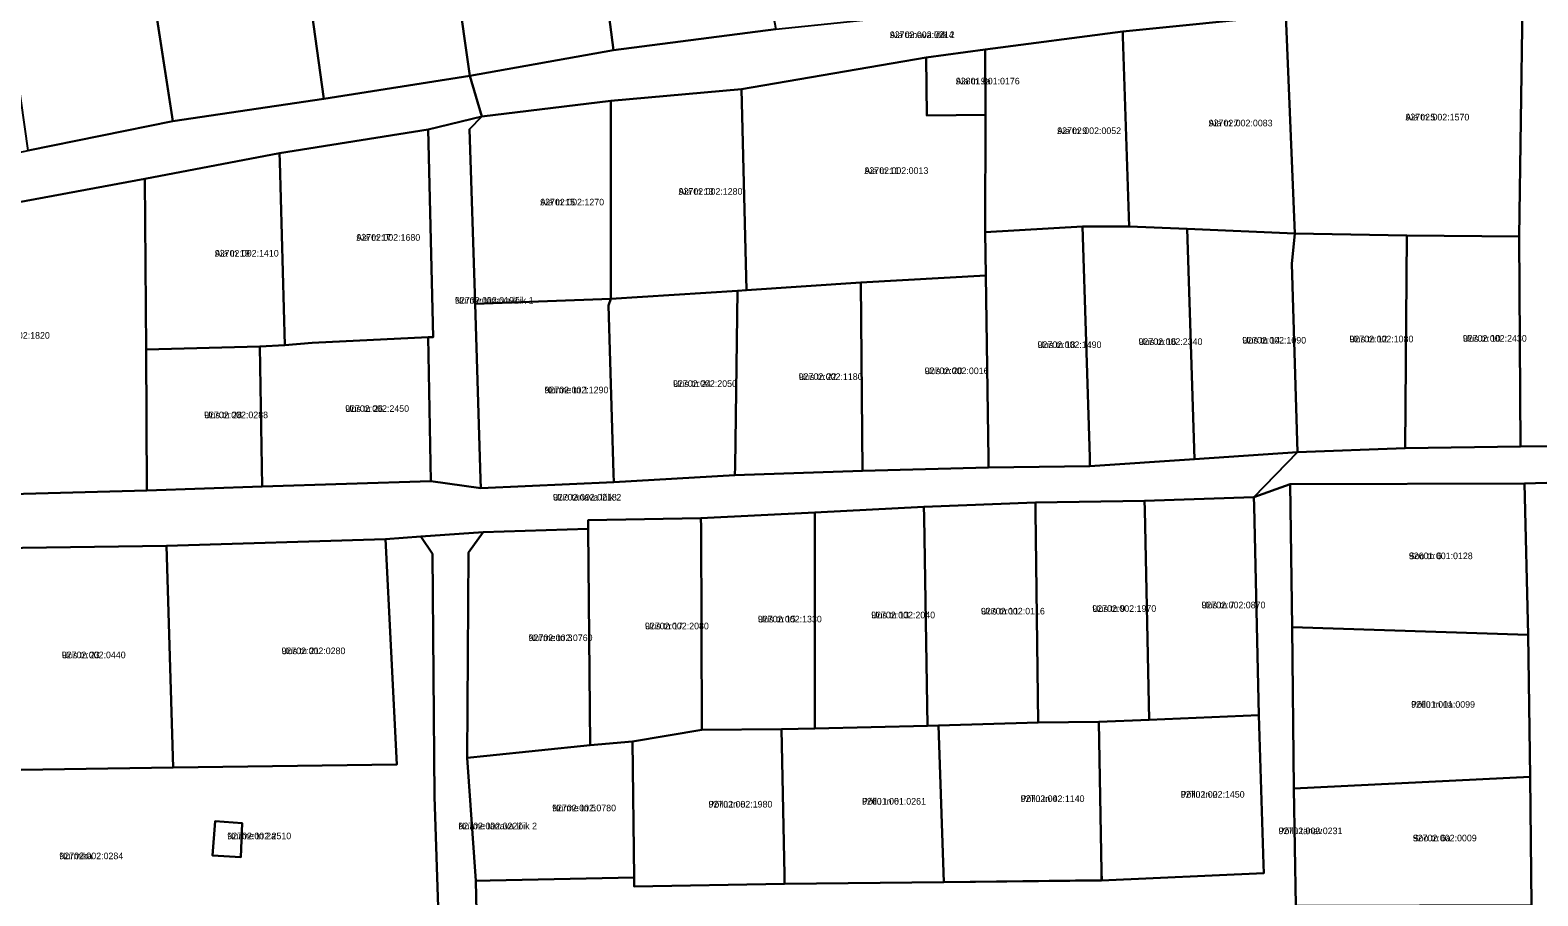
# Model space of a CAD drawing. Extents: x 615668 to 650289, y 6528908 to 6565939.
# Drawn here: x 628269.6 to 628611.8, y 6556139.7 to 6556336.2 of the extents above; entities that cross this region are included whole.
import ezdxf

# ---------------------------------------------------------------- set-up
doc = ezdxf.new("R2010")
doc.units = 0
for name, color, linetype in [('L_AADRESS', 7, 'Continuous'), ('PIIR', 7, 'Continuous'), ('TUNNUS', 7, 'Continuous')]:
    doc.layers.add(name, color=color, linetype=linetype)

msp = doc.modelspace()

# ---------------------------------------------------------------- linework, layer by layer
at = {"layer": 'PIIR'}
for points in [[(628402.02, 6556331.66), (628394.45, 6556390.11), (628427.95, 6556393.66), (628438.91, 6556336.43)], [(628369.45, 6556325.85), (628360.78, 6556386.55), (628377.58, 6556388.32), (628394.45, 6556390.11), (628402.02, 6556331.66)], [(628369.45, 6556325.85), (628336.3, 6556320.66), (628329.69, 6556368.05), (628327.48, 6556383.9), (628352.69, 6556385.91), (628360.78, 6556386.55)], [(628336.3, 6556320.66), (628302, 6556315.55), (628294.76, 6556362.62), (628294.62, 6556363.75), (628329.69, 6556368.05)], [(628262.17, 6556360.83), (628286.06, 6556362.6), (628294.62, 6556363.75), (628302, 6556315.55), (628269.18, 6556308.92), (628263.49, 6556349.22)], [(628369.45, 6556325.85), (628402.02, 6556331.66), (628438.91, 6556336.43), (628454.99, 6556338.1), (628499.26, 6556342.73), (628518.54, 6556345.4), (628521.42, 6556345.66), (628550.07, 6556348.55), (628583.13, 6556351.45), (628588.61, 6556351.54), (628613.32, 6556352.2), (628617.38, 6556341.82), (628608.35, 6556342.06), (628554.61, 6556339.61), (628517.62, 6556335.92), (628486.41, 6556331.82), (628472.97, 6556329.99), (628431.06, 6556322.79), (628401.41, 6556320.14), (628372.17, 6556316.63)], [(628517.62, 6556335.92), (628554.61, 6556339.61), (628556.65, 6556290.09), (628532.21, 6556291.1), (628519.1, 6556291.63), (628517.65, 6556334.77)], [(628556.65, 6556290.09), (628554.61, 6556339.61), (628608.35, 6556342.06), (628607.63, 6556289.38), (628582.13, 6556289.58)], [(628617.38, 6556341.82), (628619.17, 6556299.87), (628618.82, 6556245.13), (628621.11, 6556241.84), (628607.91, 6556241.68), (628607.63, 6556289.38), (628608.35, 6556342.06)], [(628486.41, 6556331.82), (628517.62, 6556335.92), (628517.65, 6556334.77), (628519.1, 6556291.63), (628508.5, 6556291.64), (628486.4, 6556290.34), (628486.5, 6556316.96)], [(628432.2, 6556277.17), (628431.06, 6556322.79), (628472.97, 6556329.99), (628473.19, 6556316.83), (628486.5, 6556316.96), (628486.4, 6556290.34), (628486.55, 6556280.55), (628458.15, 6556278.92)], [(628472.97, 6556329.99), (628486.41, 6556331.82), (628486.5, 6556316.96), (628473.19, 6556316.83)], [(628116.78, 6556276.3), (628127.45, 6556279.02), (628161.18, 6556285.75), (628193.23, 6556292.27), (628215.47, 6556296.93), (628241.75, 6556303.04), (628269.18, 6556308.92), (628302, 6556315.55), (628336.3, 6556320.66), (628369.45, 6556325.85), (628372.17, 6556316.63), (628359.94, 6556313.66), (628326.25, 6556308.32), (628295.63, 6556302.48), (628222.97, 6556288.97), (628167.18, 6556276.26), (628166.92, 6556277.13), (628127.61, 6556268.99), (628117.78, 6556267.72)], [(628401.41, 6556320.14), (628431.06, 6556322.79), (628432.2, 6556277.17), (628430.2, 6556277.01), (628401.4, 6556275.22)], [(628369.38, 6556313.76), (628372.17, 6556316.63), (628401.41, 6556320.14), (628401.4, 6556275.22), (628370.64, 6556274.1)], [(628359.94, 6556313.66), (628372.17, 6556316.63), (628369.38, 6556313.76), (628370.64, 6556274.1), (628371.84, 6556234.29), (628371.9, 6556232.29), (628360.57, 6556233.84), (628359.94, 6556266.5), (628361.06, 6556266.55)], [(628359.94, 6556313.66), (628361.06, 6556266.55), (628359.94, 6556266.5), (628333.64, 6556265.27), (628327.43, 6556264.7), (628326.31, 6556306.34), (628326.25, 6556308.32)], [(628295.63, 6556302.48), (628326.25, 6556308.32), (628326.31, 6556306.34), (628327.43, 6556264.7), (628321.74, 6556264.39), (628295.97, 6556263.72)], [(628223.57, 6556229.86), (628222.98, 6556288.5), (628222.97, 6556288.97), (628295.63, 6556302.48), (628295.97, 6556263.72), (628296.13, 6556231.76), (628251.22, 6556230.55)], [(628508.5, 6556291.64), (628510.13, 6556239.26), (628510.19, 6556237.26), (628487.18, 6556236.92), (628487.15, 6556238.92), (628486.55, 6556280.55), (628486.4, 6556290.34)], [(628510.13, 6556239.26), (628508.5, 6556291.64), (628519.1, 6556291.63), (628532.21, 6556291.1), (628533.92, 6556238.84), (628510.19, 6556237.26)], [(628532.21, 6556291.1), (628556.65, 6556290.09), (628556.04, 6556283.17), (628557.28, 6556240.42), (628533.92, 6556238.84)], [(628556.04, 6556283.17), (628556.65, 6556290.09), (628582.13, 6556289.58), (628581.74, 6556241.37), (628557.28, 6556240.42)], [(628582.13, 6556289.58), (628607.63, 6556289.38), (628607.91, 6556241.68), (628581.74, 6556241.37)], [(628429.63, 6556237.19), (628430.2, 6556277.01), (628432.2, 6556277.17), (628458.15, 6556278.92), (628458.53, 6556236.16), (628429.6, 6556235.19)], [(628458.53, 6556236.16), (628458.15, 6556278.92), (628486.55, 6556280.55), (628487.15, 6556238.92), (628487.18, 6556236.92)], [(628371.84, 6556234.29), (628370.64, 6556274.1), (628401.4, 6556275.22), (628400.91, 6556273.69), (628402.03, 6556235.6), (628402.09, 6556233.6), (628371.9, 6556232.29)], [(628402.03, 6556235.6), (628400.91, 6556273.69), (628401.4, 6556275.22), (628430.2, 6556277.01), (628429.63, 6556237.19), (628429.6, 6556235.19), (628402.09, 6556233.6)], [(628295.97, 6556263.72), (628321.74, 6556264.39), (628322.26, 6556232.63), (628296.13, 6556231.76)], [(628321.74, 6556264.39), (628327.43, 6556264.7), (628333.64, 6556265.27), (628359.94, 6556266.5), (628360.57, 6556233.84), (628322.26, 6556232.63)], [(628742.72, 6556235.1), (628740.01, 6556238.08), (628738.77, 6556234.25), (628736.92, 6556235.8), (628707.91, 6556235.32), (628678.17, 6556235.14), (628673.59, 6556234.1), (628616.36, 6556233.56), (628608.85, 6556233.28), (628555.62, 6556233.14), (628547.38, 6556230.2), (628557.28, 6556240.42), (628581.74, 6556241.37), (628607.91, 6556241.68), (628621.11, 6556241.84), (628641.56, 6556242.21), (628663.69, 6556242.63), (628686.39, 6556242.91), (628739.87, 6556243.93), (628739.55, 6556242.37), (628743.81, 6556242.51)], [(628608.85, 6556233.28), (628609.65, 6556199), (628556.08, 6556200.7), (628555.62, 6556233.14)], [(628616.36, 6556233.56), (628616.56, 6556165.75), (628616.4, 6556137.36), (628616.36, 6556130.89), (628616.23, 6556108.71), (628610.81, 6556105.7), (628610.63, 6556120.99), (628610.43, 6556137.57), (628610.09, 6556166.71), (628609.65, 6556199), (628608.85, 6556233.28)], [(628251.22, 6556230.55), (628251.48, 6556218.47), (628252.68, 6556168.09), (628302.09, 6556168.82), (628352.81, 6556169.57), (628350.31, 6556220.66), (628358.28, 6556221.27), (628360.98, 6556217.37), (628361.36, 6556162.3), (628363.16, 6556109.78), (628368.29, 6556078.96), (628130.78, 6556065.52), (628125.16, 6556114.7), (628191.72, 6556114.13), (628189.74, 6556175.67), (628224.11, 6556176.37), (628223.57, 6556229.86)], [(628523.62, 6556179.64), (628522.61, 6556227.35), (628522.54, 6556229.35), (628547.38, 6556230.2), (628547.42, 6556228.15), (628548.48, 6556180.76)], [(628421.88, 6556225.42), (628447.73, 6556226.74), (628447.73, 6556224.74), (628447.73, 6556177.7), (628440.14, 6556177.53), (628422.06, 6556177.37), (628421.91, 6556223.43)], [(628447.73, 6556224.74), (628447.73, 6556226.74), (628472.47, 6556228.02), (628472.52, 6556225.68), (628473.32, 6556178.34), (628447.73, 6556177.7)], [(628497.83, 6556228.97), (628497.85, 6556226.97), (628498.41, 6556179.04), (628475.77, 6556178.4), (628473.32, 6556178.34), (628472.52, 6556225.68), (628472.47, 6556228.02)], [(628497.85, 6556226.97), (628497.83, 6556228.97), (628522.54, 6556229.35), (628522.61, 6556227.35), (628523.62, 6556179.64), (628512.19, 6556179.2), (628498.41, 6556179.04)], [(628373.29, 6556171.5), (628368.82, 6556171.04), (628369.15, 6556217.62), (628372.48, 6556222.28), (628396.28, 6556223.01), (628396.73, 6556173.95)], [(628396.73, 6556173.95), (628396.28, 6556223.01), (628396.28, 6556225.01), (628421.88, 6556225.42), (628421.91, 6556223.43), (628422.06, 6556177.37), (628406.33, 6556174.75)], [(628251.48, 6556218.47), (628300.53, 6556219.2), (628302.09, 6556168.82), (628252.68, 6556168.09)], [(628350.31, 6556220.66), (628352.81, 6556169.57), (628302.09, 6556168.82), (628300.53, 6556219.2)], [(628372.48, 6556222.28), (628369.15, 6556217.62), (628368.82, 6556171.04), (628370.81, 6556143.09), (628371, 6556132.6), (628370.96, 6556109.93), (628375.36, 6556079.42), (628368.29, 6556078.96), (628363.16, 6556109.78), (628361.36, 6556162.3), (628360.98, 6556217.37), (628358.28, 6556221.27)], [(628556.48, 6556164.12), (628556.08, 6556200.7), (628609.65, 6556199), (628610.09, 6556166.71)], [(628475.77, 6556178.4), (628477.01, 6556142.86), (628440.81, 6556142.47), (628440.84, 6556144.51), (628440.14, 6556177.53), (628447.73, 6556177.7), (628473.32, 6556178.34)], [(628475.77, 6556178.4), (628498.41, 6556179.04), (628512.19, 6556179.2), (628512.8, 6556145.27), (628512.84, 6556143.26), (628477.01, 6556142.86)], [(628512.8, 6556145.27), (628512.19, 6556179.2), (628523.62, 6556179.64), (628548.48, 6556180.76), (628549.56, 6556146.84), (628549.62, 6556144.84), (628512.78, 6556143.23)], [(628370.81, 6556143.09), (628368.82, 6556171.04), (628373.29, 6556171.5), (628396.73, 6556173.95), (628406.33, 6556174.75), (628406.7, 6556143.86), (628374.02, 6556143.23)], [(628406.73, 6556141.86), (628406.7, 6556143.86), (628406.33, 6556174.75), (628422.06, 6556177.37), (628440.14, 6556177.53), (628440.84, 6556144.51), (628440.81, 6556142.47)], [(628556.48, 6556164.12), (628610.09, 6556166.71), (628610.43, 6556137.57), (628559.51, 6556137.48), (628556.9, 6556137.47)], [(628317.72, 6556156.25), (628317.44, 6556148.48), (628311.02, 6556148.89), (628311.61, 6556156.65)], [(628311.61, 6556156.65), (628311.02, 6556148.89), (628317.44, 6556148.48), (628317.72, 6556156.25)]]:
    msp.add_lwpolyline(points, close=True, dxfattribs=at)
for points in [[(628251.22, 6556230.55), (628296.13, 6556231.76), (628322.26, 6556232.63), (628360.57, 6556233.84), (628371.9, 6556232.29), (628402.09, 6556233.6), (628429.6, 6556235.19), (628458.53, 6556236.16), (628487.18, 6556236.92), (628510.19, 6556237.26), (628533.92, 6556238.84), (628557.28, 6556240.42), (628547.38, 6556230.2), (628522.54, 6556229.35), (628497.83, 6556228.97), (628472.47, 6556228.02), (628447.73, 6556226.74), (628421.88, 6556225.42), (628396.28, 6556225.01), (628396.28, 6556223.01), (628372.48, 6556222.28), (628358.28, 6556221.27), (628350.31, 6556220.66), (628300.53, 6556219.2), (628251.48, 6556218.47)], [(628371, 6556132.6), (628370.81, 6556143.09), (628374.02, 6556143.23), (628406.7, 6556143.86), (628406.73, 6556141.86), (628440.81, 6556142.47), (628477.01, 6556142.86), (628512.78, 6556143.23), (628549.62, 6556144.84), (628549.56, 6556146.84), (628548.48, 6556180.76), (628547.42, 6556228.15), (628547.38, 6556230.2), (628555.62, 6556233.14), (628556.08, 6556200.7), (628556.48, 6556164.12), (628556.9, 6556137.47)]]:
    msp.add_lwpolyline(points, dxfattribs=at)

# ---------------------------------------------------------------- texts
at = {"layer": 'L_AADRESS'}
for s, p in [('Aia tänava lõik 2', (628464.75, 6556334.41)), ('Aia tn 9a', (628479.73, 6556323.9)), ('Aia tn 7', (628537.13, 6556314.38)), ('Aia tn 5', (628581.79, 6556315.72)), ('Aia tn 9', (628502.75, 6556312.63)), ('Aia tn 11', (628458.99, 6556303.58)), ('Aia tn 15', (628385.39, 6556296.43)), ('Aia tn 13', (628416.8, 6556298.85)), ('Aia tn 17', (628343.66, 6556288.41)), ('Aia tn 19', (628311.53, 6556284.82)), ('Nurme tänava lõik 1', (628366.05, 6556274.12)), ('Uus tn 10', (628594.82, 6556265.5)), ('Uus tn 18', (628498.29, 6556264.06)), ('Uus tn 16', (628521.21, 6556264.77)), ('Uus tn 14', (628544.75, 6556265.08)), ('Uus tn 12', (628569.09, 6556265.36)), ('Uus tn 24', (628415.55, 6556255.24)), ('Uus tn 22', (628444.07, 6556256.82)), ('Uus tn 20', (628472.66, 6556258.14)), ('Nurme tn 1', (628386.37, 6556253.8)), ('Uus tn 26', (628341.12, 6556249.57)), ('Uus tn 28', (628309.11, 6556248.13)), ('Uue tänava lõik 2', (628388.28, 6556229.45)), ('Soo tn 6', (628582.56, 6556216.14)), ('Uus tn 9', (628510.72, 6556204.18)), ('Uus tn 7', (628535.51, 6556204.98)), ('Uus tn 15', (628434.8, 6556201.78)), ('Uus tn 13', (628460.52, 6556202.71)), ('Uus tn 11', (628485.44, 6556203.59)), ('Nurme tn 3', (628382.77, 6556197.54)), ('Uus tn 17', (628409.17, 6556200.22)), ('Uus tn 23', (628276.79, 6556193.65)), ('Uus tn 21', (628326.67, 6556194.58)), ('Põllu tn 1a', (628583.08, 6556182.41)), ('Põllu tn 8', (628423.59, 6556159.77)), ('Põllu tn 6', (628458.45, 6556160.43)), ('Põllu tn 4', (628494.45, 6556161.03)), ('Põllu tn 2', (628530.79, 6556162)), ('Nurme tn 5', (628388.1, 6556158.92)), ('Nurme tn 2a', (628314.37, 6556152.57)), ('Nurme tänava lõik 2', (628366.82, 6556154.83)), ('Põllu tänav', (628552.99, 6556153.72)), ('Soo tn 6a', (628583.47, 6556152.09)), ('Nurmika', (628276.24, 6556148.04))]:
    msp.add_text(s, height=1.5, dxfattribs=at).set_placement(p)
at = {"layer": 'TUNNUS'}
for s, p in [('92702:002:0214', (628464.75, 6556334.41)), ('92801:001:0176', (628479.73, 6556323.9)), ('92702:002:0083', (628537.13, 6556314.38)), ('92702:002:1570', (628581.79, 6556315.72)), ('92702:002:0052', (628502.75, 6556312.63)), ('92702:002:0013', (628458.99, 6556303.58)), ('92702:002:1270', (628385.39, 6556296.43)), ('92702:002:1280', (628416.8, 6556298.85)), ('92702:002:1680', (628343.66, 6556288.41)), ('92702:002:1410', (628311.53, 6556284.82)), ('92702:002:0191', (628366.05, 6556274.12)), ('92702:002:1820', (628259.58, 6556266.17)), ('92702:002:2430', (628594.82, 6556265.5)), ('92702:002:1490', (628498.29, 6556264.06)), ('92702:002:2340', (628521.21, 6556264.77)), ('92702:002:1090', (628544.75, 6556265.08)), ('92702:002:1080', (628569.09, 6556265.36)), ('92702:002:2050', (628415.55, 6556255.24)), ('92702:002:1180', (628444.07, 6556256.82)), ('92702:002:0016', (628472.66, 6556258.14)), ('92702:002:1290', (628386.37, 6556253.8)), ('92702:002:2450', (628341.12, 6556249.57)), ('92702:002:0288', (628309.11, 6556248.13)), ('92702:002:0218', (628388.28, 6556229.45)), ('92601:001:0128', (628582.56, 6556216.14)), ('92702:002:1970', (628510.72, 6556204.18)), ('92702:002:0870', (628535.51, 6556204.98)), ('92702:002:1330', (628434.8, 6556201.78)), ('92702:002:2040', (628460.52, 6556202.71)), ('92702:002:0116', (628485.44, 6556203.59)), ('92702:002:0760', (628382.77, 6556197.54)), ('92702:002:2080', (628409.17, 6556200.22)), ('92702:002:0440', (628276.79, 6556193.65)), ('92702:002:0280', (628326.67, 6556194.58)), ('92601:001:0099', (628583.08, 6556182.41)), ('92702:002:1980', (628423.59, 6556159.77)), ('92601:001:0261', (628458.45, 6556160.43)), ('92702:002:1140', (628494.45, 6556161.03)), ('92702:002:1450', (628530.79, 6556162)), ('92702:002:0780', (628388.1, 6556158.92)), ('92702:002:2510', (628314.37, 6556152.57)), ('92702:002:0221', (628366.82, 6556154.83)), ('92702:002:0231', (628552.99, 6556153.72)), ('92702:002:0009', (628583.47, 6556152.09)), ('92702:002:0284', (628276.24, 6556148.04))]:
    msp.add_text(s, height=1.5, dxfattribs=at).set_placement(p)

doc.saveas('drawing.dxf')
